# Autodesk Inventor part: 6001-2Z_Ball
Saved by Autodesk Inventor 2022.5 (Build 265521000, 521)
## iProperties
Created: 2024-12
Part Number: 6001-2Z_Ball
Material: Generic
Document SubType Name: Modeling
Designer: AdminForWorker
Density: 1 g/cm^3
Appearance: Default
Title: 6001-2Z_Ball
Author: AdminForWorker
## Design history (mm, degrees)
feature "Body1"
body "Solid1"
